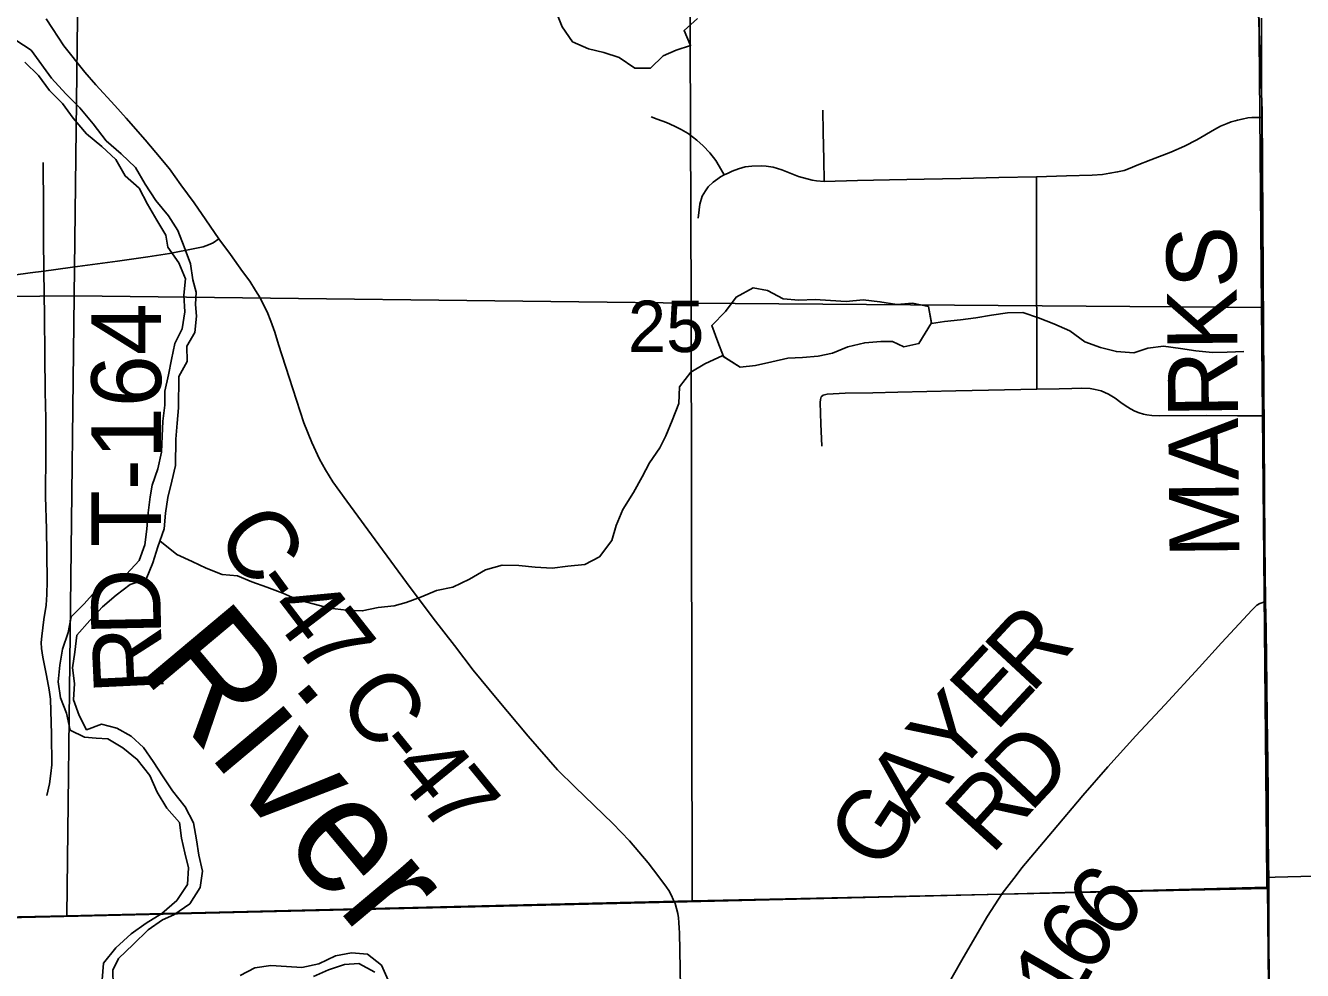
# Model space of a CAD drawing. Extents: x 0 to 34, y 0 to 22.
# Drawn here: x 3.782 to 4.301, y 17.804 to 18.189 of the extents above; entities that cross this region are included whole.
import ezdxf

# ---------------------------------------------------------------- set-up
doc = ezdxf.new("R2010")
doc.units = 0
for name, color, linetype in [('GM_X_County_Road', 7, 'Continuous'), ('GM_X_County_Road_Text', 7, 'Continuous'), ('GM_X_Major_River', 7, 'Continuous'), ('GM_X_Major_River_Text', 7, 'Continuous'), ('GM_X_Minor_Lake', 7, 'Continuous'), ('GM_X_Minor_River', 7, 'Continuous'), ('GM_X_Rail_Line_Text', 7, 'Continuous'), ('GM_X_Section', 7, 'Continuous'), ('GM_X_Section_Text', 7, 'Continuous'), ('GM_X_Township', 7, 'Continuous'), ('GM_X_Township_Road', 7, 'Continuous'), ('GM_X_Township_Road_Text', 7, 'Continuous')]:
    doc.layers.add(name, color=color, linetype=linetype)

msp = doc.modelspace()

# ---------------------------------------------------------------- linework, layer by layer
at = {"layer": 'GM_X_County_Road'}
msp.add_line((4.28732, 17.83823), (4.28729, 17.84071), dxfattribs=at)
for points in [[(4.04573, 17.83146), (4.04505, 17.83315), (4.04432, 17.83475), (4.04318, 17.83675), (4.04228, 17.83819), (4.03921, 17.84236), (4.03483, 17.84809), (4.02721, 17.85693), (4.02038, 17.86409), (4.00514, 17.87879), (3.99793, 17.88587), (3.98598, 17.89955), (3.97335, 17.91468), (3.96357, 17.9264), (3.95596, 17.93644), (3.94728, 17.94756), (3.9365, 17.96213), (3.9253, 17.97737), (3.91216, 17.99518), (3.90656, 18.00306), (3.90361, 18.0079), (3.90117, 18.01232), (3.89793, 18.01902), (3.89468, 18.0271), (3.88871, 18.04546), (3.88449, 18.05894), (3.88289, 18.06395), (3.88136, 18.06847), (3.87978, 18.07229), (3.87822, 18.0754), (3.877, 18.07797), (3.8751, 18.08088), (3.87275, 18.08467), (3.86984, 18.08862), (3.86484, 18.09549), (3.86012, 18.10197), (3.85483, 18.10963), (3.85009, 18.11659), (3.84475, 18.12393), (3.84003, 18.13038), (3.83458, 18.13705), (3.83023, 18.14227), (3.82246, 18.15103), (3.81778, 18.15621), (3.81011, 18.16465), (3.80567, 18.16974), (3.79713, 18.1805), (3.7925, 18.18753), (3.78987, 18.1915)], [(4.28729, 17.84071), (4.28707, 17.85808), (4.28698, 17.87687), (4.28689, 17.8887), (4.28661, 17.90707), (4.28651, 17.92002), (4.28623, 17.94292), (4.28595, 17.95442), (4.28562, 17.97842), (4.28548, 18.00015), (4.2853, 18.01806), (4.28536, 18.02988), (4.2853, 18.03377), (4.28523, 18.04139), (4.28514, 18.053), (4.285, 18.06936), (4.28479, 18.08779), (4.28455, 18.11004), (4.2845, 18.13902), (4.28446, 18.15131), (4.28436, 18.1673), (4.28432, 18.1917)], [(3.77665, 18.0872), (3.78339, 18.08808), (3.78894, 18.0888), (3.79379, 18.08938), (3.80057, 18.09035), (3.81894, 18.09287), (3.83131, 18.09461), (3.84007, 18.09595), (3.85105, 18.09813), (3.85379, 18.09873), (3.85598, 18.09945), (3.85784, 18.10029), (3.86012, 18.10197)], [(4.28812, 17.71671), (4.28792, 17.7282), (4.2878, 17.7445), (4.28772, 17.75718), (4.28764, 17.77048), (4.28759, 17.77872), (4.28749, 17.79424), (4.28734, 17.82364), (4.28732, 17.83823)], [(4.04833, 17.77327), (4.0478, 17.8051), (4.04757, 17.81954), (4.04749, 17.82145), (4.04731, 17.8237), (4.04712, 17.82565), (4.04682, 17.82738), (4.04638, 17.82944), (4.04573, 17.83146)]]:
    msp.add_lwpolyline(points, dxfattribs=at)
at = {"layer": 'GM_X_Major_River'}
for points in [[(3.84604, 18.09864), (3.84341, 18.10532), (3.83964, 18.11123), (3.83455, 18.11754), (3.83021, 18.12422), (3.82626, 18.1309), (3.82039, 18.13645), (3.81434, 18.14181), (3.80906, 18.14869), (3.80358, 18.15518), (3.79792, 18.16092), (3.79206, 18.16723), (3.78376, 18.17869), (3.77751, 18.18272)], [(3.78127, 18.17376), (3.78675, 18.1684), (3.79128, 18.16229), (3.79657, 18.15694), (3.8009, 18.15102), (3.80638, 18.14471), (3.81262, 18.13954), (3.8183, 18.13418), (3.82206, 18.1275), (3.82773, 18.12252), (3.83112, 18.11604), (3.83489, 18.10955), (3.83865, 18.10344), (3.83939, 18.09849), (3.84392, 18.09219), (3.84654, 18.08571), (3.84594, 18.07905), (3.84629, 18.0722), (3.8453, 18.06536), (3.84223, 18.05929), (3.84087, 18.05283), (3.8397, 18.04656), (3.83815, 18.03991), (3.83812, 18.0342), (3.83733, 18.02774), (3.83711, 18.02166), (3.83689, 18.01519), (3.83533, 18.00835), (3.83302, 18.00171), (3.83224, 17.99695), (3.83145, 17.99049), (3.83084, 17.98384), (3.83005, 17.97737), (3.82774, 17.97111), (3.82259, 17.96543), (3.81593, 17.963), (3.80983, 17.95846), (3.80543, 17.95335), (3.80009, 17.94806), (3.79892, 17.94179), (3.7966, 17.93495), (3.79543, 17.92849), (3.79483, 17.92165), (3.79575, 17.91518), (3.79819, 17.90888), (3.79967, 17.90203), (3.80554, 17.89914), (3.81029, 17.89874), (3.81504, 17.89852), (3.8211, 17.89487), (3.82696, 17.89009), (3.83206, 17.88359), (3.83506, 17.87673), (3.83902, 17.87024), (3.84412, 17.8645), (3.84503, 17.85803), (3.84633, 17.85213), (3.84782, 17.84603), (3.84741, 17.83919), (3.84301, 17.83274), (3.83691, 17.82745), (3.83062, 17.82349), (3.82452, 17.81915), (3.81823, 17.81348), (3.81326, 17.80723), (3.81265, 17.80039)], [(3.8172, 17.79808), (3.81704, 17.80436), (3.81934, 17.8091), (3.82526, 17.81477), (3.83137, 17.82083), (3.83727, 17.82479), (3.84184, 17.82685), (3.84832, 17.83138), (3.85253, 17.83802), (3.85351, 17.84467), (3.85203, 17.85114), (3.85111, 17.85743), (3.84981, 17.86428), (3.84643, 17.87077), (3.84133, 17.87726), (3.83756, 17.88299), (3.83341, 17.88929), (3.82945, 17.89502), (3.82454, 17.89961), (3.81867, 17.90287), (3.81241, 17.90443), (3.80632, 17.90218), (3.80331, 17.90791), (3.80106, 17.91438), (3.80147, 17.92104), (3.80056, 17.92732), (3.80154, 17.93378), (3.80233, 17.94063), (3.80768, 17.94668), (3.81283, 17.95217), (3.81837, 17.9569), (3.82408, 17.96124), (3.83055, 17.96349), (3.83324, 17.97013), (3.83537, 17.97658), (3.83787, 17.98399), (3.83847, 17.99026), (3.83945, 17.99673), (3.84101, 18.00337), (3.84256, 18.00964), (3.84261, 18.02048), (3.84321, 18.02695), (3.84381, 18.03322), (3.84388, 18.04597), (3.84732, 18.05203), (3.84717, 18.05831), (3.85042, 18.06381), (3.85103, 18.07046), (3.85067, 18.07522), (3.85088, 18.08017), (3.84958, 18.08531), (3.84866, 18.09178), (3.84604, 18.09864)], [(3.92907, 17.80031), (3.92626, 17.80642), (3.92058, 17.81082), (3.91413, 17.81143), (3.90766, 17.81013), (3.90081, 17.80694), (3.89396, 17.80545), (3.8877, 17.80587), (3.88124, 17.80628), (3.87478, 17.80537), (3.86888, 17.80217)], [(3.89869, 17.80181), (3.90478, 17.80444), (3.91125, 17.80669), (3.91714, 17.80704), (3.92358, 17.80358)]]:
    msp.add_lwpolyline(points, dxfattribs=at)
at = {"layer": 'GM_X_Minor_Lake'}
for points in [[(4.1501, 18.06769), (4.14884, 18.07433), (4.14239, 18.0757), (4.13593, 18.07517), (4.1291, 18.07634), (4.12227, 18.07714), (4.11543, 18.07642), (4.10897, 18.07684), (4.10271, 18.07725), (4.09606, 18.07691), (4.08979, 18.07751), (4.08335, 18.08097), (4.07747, 18.08196), (4.07061, 18.07819), (4.06622, 18.07232), (4.06068, 18.06664), (4.06312, 18.05997), (4.06543, 18.05402)], [(4.15012, 18.06754), (4.14884, 18.07433), (4.14239, 18.0757), (4.13593, 18.07517), (4.1291, 18.07634), (4.12227, 18.07714), (4.11543, 18.07642), (4.10897, 18.07684), (4.10271, 18.07725), (4.09606, 18.07691), (4.08979, 18.07751), (4.08335, 18.08097), (4.07747, 18.08196), (4.07061, 18.07819), (4.06622, 18.07232), (4.06068, 18.06664), (4.06312, 18.05997), (4.06543, 18.05401)], [(4.06537, 18.05406), (4.07218, 18.04965), (4.07845, 18.05037), (4.08511, 18.05186), (4.09157, 18.05335), (4.09765, 18.05369), (4.10392, 18.05423), (4.10981, 18.05534), (4.11609, 18.05797), (4.12294, 18.05964), (4.1294, 18.06017), (4.13415, 18.06015), (4.13889, 18.05803), (4.14497, 18.05933), (4.15012, 18.06773)], [(4.06543, 18.05402), (4.07218, 18.04965), (4.07845, 18.05037), (4.08511, 18.05186), (4.09157, 18.05335), (4.09765, 18.05369), (4.10392, 18.05423), (4.10981, 18.05534), (4.11609, 18.05797), (4.12294, 18.05964), (4.1294, 18.06017), (4.13415, 18.06015), (4.13889, 18.05803), (4.14497, 18.05933), (4.1501, 18.06769)]]:
    msp.add_lwpolyline(points, dxfattribs=at)
at = {"layer": 'GM_X_Minor_River'}
for points in [[(3.99732, 18.19426), (3.99982, 18.18818), (4.00403, 18.18211), (4.0105, 18.17928), (4.01677, 18.17778), (4.02305, 18.17571), (4.02934, 18.17136), (4.0358, 18.17138), (4.0409, 18.17635), (4.04621, 18.17865), (4.05209, 18.18057), (4.0494, 18.18665), (4.05489, 18.19162)], [(4.15012, 18.06754), (4.15537, 18.06835), (4.16183, 18.06894), (4.16809, 18.06973), (4.17454, 18.07089), (4.181, 18.07187), (4.18726, 18.07189), (4.19354, 18.06982), (4.19982, 18.06737), (4.20629, 18.06454), (4.21239, 18.06), (4.21886, 18.05774), (4.22533, 18.05605), (4.23236, 18.05551), (4.23804, 18.05743), (4.2445, 18.05822), (4.25134, 18.05729), (4.25761, 18.05636), (4.26445, 18.05563), (4.27034, 18.05584), (4.27718, 18.05605)], [(3.83612, 17.97907), (3.843, 17.97344), (3.84928, 17.97061), (3.85499, 17.96797), (3.86146, 17.96533), (3.86773, 17.96478), (3.87363, 17.96233), (3.87972, 17.96026), (3.88619, 17.95781), (3.89228, 17.95498), (3.89855, 17.95348), (3.90521, 17.95161), (3.91205, 17.95087), (3.91851, 17.95051), (3.92496, 17.95187), (3.93142, 17.95265), (3.93635, 17.954), (3.9426, 17.95631), (3.94867, 17.9588), (3.95531, 17.96016), (3.96214, 17.96341), (3.96857, 17.96724), (3.9754, 17.96917), (3.98224, 17.969), (3.98889, 17.96827), (3.99573, 17.96791), (4.00219, 17.9687), (4.00902, 17.96948), (4.01508, 17.97255), (4.01999, 17.97922), (4.02186, 17.98532), (4.02449, 17.99179), (4.02882, 17.99866), (4.0324, 18.00514), (4.03541, 18.01085), (4.03956, 18.01695), (4.04201, 18.02172), (4.04464, 18.028), (4.04727, 18.03486), (4.04762, 18.04171), (4.05215, 18.04762), (4.05783, 18.05107), (4.06514, 18.0545)]]:
    msp.add_lwpolyline(points, dxfattribs=at)
at = {"layer": 'GM_X_Rail_Line_Text'}
for points in [[(2.77875, 17.80661), (3.04126, 17.80913), (3.53178, 17.8199), (4.04512, 17.83208), (4.17864, 17.83524), (4.28678, 17.83811), (4.28692, 17.84212), (4.28581, 17.95524), (4.28464, 18.15407), (4.27642, 18.36992), (4.27726, 18.56476), (4.27587, 18.8261), (4.27859, 19.13014), (4.27679, 19.3807), (4.2769, 19.4129), (4.27672, 19.50175), (4.27627, 19.60888)], [(4.29417, 16.81303), (4.29258, 17.16739), (4.29139, 17.31008), (4.28969, 17.51278), (4.28798, 17.71737), (4.28678, 17.83811), (4.17864, 17.83524), (4.04512, 17.83208), (3.53178, 17.8199), (3.04126, 17.80913), (2.77875, 17.80661), (2.75328, 17.8059), (2.73257, 17.80595), (2.72272, 17.80515), (2.29055, 17.79989), (2.19668, 17.79909), (2.1, 17.79837), (2.1, 15.5976)]]:
    msp.add_lwpolyline(points, dxfattribs=at)
at = {"layer": 'GM_X_Section'}
for points in [[(3.80425, 18.32752), (3.8013, 18.0787), (3.54907, 18.0763), (3.54412, 18.32749)], [(4.0513, 18.32631), (4.0523, 18.07571), (3.8013, 18.0787), (3.80425, 18.32752)], [(4.28218, 18.32518), (4.28428, 18.07404), (4.0523, 18.07571), (4.0513, 18.32631)], [(3.8013, 18.0787), (3.79831, 17.82652), (3.76549, 17.82574), (3.55097, 17.82042), (3.54907, 18.0763)], [(4.0523, 18.07571), (4.05273, 17.83262), (4.02343, 17.83192), (3.79831, 17.82652), (3.8013, 18.0787)], [(4.28428, 18.07404), (4.28652, 17.84087), (4.28654, 17.83764), (4.05273, 17.83262), (4.0523, 18.07571)]]:
    msp.add_lwpolyline(points, close=True, dxfattribs=at)
at = {"layer": 'GM_X_Township'}
for points in [[(5.23962, 17.86489), (4.75674, 17.85444), (4.28987, 17.8422), (4.28692, 17.84212), (4.28581, 17.95524), (4.28464, 18.15407), (4.27642, 18.36992), (4.27726, 18.56476), (4.27587, 18.8261), (4.27859, 19.13014), (4.27679, 19.3807), (4.2769, 19.4129), (4.27672, 19.50175), (4.27627, 19.60888)], [(4.29417, 16.81303), (4.29258, 17.16739), (4.29139, 17.31008), (4.28969, 17.51278), (4.28798, 17.71737), (4.28678, 17.83811), (4.28685, 17.84011), (4.28692, 17.84212), (4.28987, 17.8422), (4.75674, 17.85444), (5.23962, 17.86489), (5.68786, 17.8746), (6.14296, 17.88445), (6.51777, 17.89256), (6.52166, 17.89265), (6.52686, 17.89276), (6.71961, 17.89693), (6.72194, 17.73847), (6.72576, 17.34372), (6.73112, 16.77245)]]:
    msp.add_lwpolyline(points, dxfattribs=at)
at = {"layer": 'GM_X_Township_Road'}
msp.add_line((4.17885, 17.83555), (4.18451, 17.84287), dxfattribs=at)
for points in [[(4.03607, 18.15152), (4.03847, 18.15066), (4.04224, 18.14921), (4.04556, 18.1478), (4.04821, 18.14647), (4.05105, 18.14476), (4.05459, 18.14213), (4.05718, 18.13972), (4.0599, 18.13686), (4.06231, 18.13382), (4.06376, 18.13155), (4.06576, 18.12797)], [(4.05516, 18.1103), (4.0556, 18.11377), (4.05589, 18.11608), (4.05684, 18.11933), (4.05807, 18.12151), (4.0592, 18.12314), (4.0612, 18.12492), (4.06315, 18.12637), (4.06425, 18.12714), (4.06576, 18.12797), (4.06733, 18.12866), (4.06896, 18.12943), (4.07154, 18.13041), (4.07423, 18.13116), (4.07696, 18.13151), (4.08074, 18.13159), (4.08281, 18.13147), (4.0856, 18.13106), (4.08918, 18.12997), (4.09601, 18.12726), (4.10158, 18.12575), (4.10327, 18.12549), (4.10645, 18.1253), (4.11994, 18.1256), (4.13302, 18.12589), (4.14715, 18.1262), (4.16195, 18.12653), (4.1775, 18.12687), (4.19284, 18.12721), (4.205, 18.12757), (4.21545, 18.12789), (4.21967, 18.12813), (4.22267, 18.1286), (4.2258, 18.12918), (4.22842, 18.12976), (4.23094, 18.13071), (4.2338, 18.13184), (4.23928, 18.13405), (4.24739, 18.13718), (4.25297, 18.13963), (4.25798, 18.14226), (4.26526, 18.14637), (4.26771, 18.14774), (4.27033, 18.14886), (4.27203, 18.14953), (4.27361, 18.14999), (4.27461, 18.15025), (4.2764, 18.15068), (4.27872, 18.15112), (4.28035, 18.15126), (4.28446, 18.15131)], [(4.10645, 18.1253), (4.10627, 18.13416), (4.10604, 18.1453), (4.10585, 18.15434)], [(3.78894, 18.0888), (3.78888, 18.10197), (3.78883, 18.1147), (3.78864, 18.13299)], [(4.19297, 18.04075), (4.19292, 18.05276), (4.19287, 18.06608), (4.1928, 18.08224), (4.19275, 18.09517), (4.19279, 18.11056), (4.19284, 18.12721)], [(3.79022, 17.87536), (3.79125, 17.88018), (3.79186, 17.88444), (3.79216, 17.88795), (3.79203, 17.90035), (3.79187, 17.90991), (3.79161, 17.91464), (3.79113, 17.91843), (3.79008, 17.92428), (3.78858, 17.93171), (3.78797, 17.9352), (3.78787, 17.93767), (3.78811, 17.94032), (3.78895, 17.94697), (3.78992, 17.9529), (3.79022, 17.9572), (3.79034, 17.96265), (3.79016, 17.9739), (3.78998, 17.98383), (3.78962, 17.99709), (3.78974, 18.01531), (3.7898, 18.02887), (3.78955, 18.03964), (3.78937, 18.05477), (3.78919, 18.07051), (3.78894, 18.0888)], [(4.10542, 18.01753), (4.10509, 18.02669), (4.10479, 18.03532), (4.10489, 18.03659), (4.10518, 18.03768)], [(4.10518, 18.03768), (4.10597, 18.03832), (4.10763, 18.0387), (4.11491, 18.03908), (4.12625, 18.03932), (4.13639, 18.03956), (4.15992, 18.04003), (4.1733, 18.04034), (4.19297, 18.04075), (4.20199, 18.04088), (4.2072, 18.04106), (4.21107, 18.04112), (4.21463, 18.041), (4.21662, 18.04064), (4.21905, 18.04002), (4.22211, 18.03875), (4.22477, 18.03714), (4.22709, 18.03535), (4.22888, 18.03405), (4.23097, 18.0327), (4.23276, 18.03183), (4.2346, 18.03109), (4.23638, 18.03059), (4.23774, 18.03027), (4.23974, 18.02999), (4.24265, 18.02989), (4.26188, 18.03001), (4.27456, 18.02994), (4.28536, 18.02988)], [(4.18451, 17.84287), (4.18689, 17.84595), (4.19932, 17.86077), (4.21158, 17.87538), (4.22188, 17.88709), (4.23323, 17.89967), (4.24495, 17.91233), (4.25893, 17.92745), (4.26801, 17.93753), (4.28053, 17.95096), (4.28244, 17.95283), (4.28368, 17.95354), (4.28595, 17.95442)], [(4.14, 17.76726), (4.14071, 17.77005), (4.14203, 17.77287), (4.15406, 17.79366), (4.16296, 17.80933), (4.17281, 17.82635), (4.17885, 17.83555)]]:
    msp.add_lwpolyline(points, dxfattribs=at)

# ---------------------------------------------------------------- texts
at = {"layer": 'GM_X_County_Road_Text'}
for s, height, rotation, p in [('MARKS', 0.028409, 90.5804, (4.27536, 17.97218)), ('C', 0.02841, 303.807, (3.8582, 17.98144)), ('-', 0.02841, 306.14, (3.8719, 17.96102)), ('4', 0.02841, 307.4059, (3.87919, 17.95105)), ('7', 0.02841, 308.1763, (3.89008, 17.93682)), ('C', 0.02841, 308.0838, (3.90756, 17.9138)), ('-', 0.02841, 309.0401, (3.92227, 17.89503)), ('4', 0.02841, 309.2328, (3.92969, 17.88589)), ('7', 0.02841, 309.2908, (3.94078, 17.87231))]:
    msp.add_text(s, height=height, rotation=rotation, dxfattribs=at).set_placement(p)
at = {"layer": 'GM_X_Major_River_Text'}
msp.add_text('River', height=0.047372, rotation=309.9777, dxfattribs=at).set_placement((3.82647, 17.9268))
at = {"layer": 'GM_X_Section_Text'}
msp.add_text('25', height=0.020928, rotation=0, dxfattribs=at).set_placement((4.02654, 18.05586))
at = {"layer": 'GM_X_Township_Road_Text'}
for s, height, rotation, p in [('T-164', 0.028409, 90, (3.83668, 17.97646)), ('D', 0.02841, 91.1913, (3.83672, 17.94068)), ('R', 0.02841, 47.1364, (4.19064, 17.91645)), ('R', 0.02841, 92.694, (3.83781, 17.91757)), ('E', 0.02841, 47.1339, (4.17618, 17.90087)), ('Y', 0.02841, 47.1436, (4.15918, 17.88254)), ('D', 0.02841, 46.9167, (4.19016, 17.86801)), ('A', 0.02841, 49.8404, (4.14329, 17.8637)), ('R', 0.02841, 47.6806, (4.17452, 17.85083)), ('G', 0.02841, 56.8717, (4.13017, 17.8435)), ('6', 0.02841, 47.7204, (4.22393, 17.81522)), ('6', 0.02841, 54.5531, (4.21435, 17.80166)), ('1', 0.02841, 59.8323, (4.20593, 17.78711))]:
    msp.add_text(s, height=height, rotation=rotation, dxfattribs=at).set_placement(p)

doc.saveas('drawing.dxf')
